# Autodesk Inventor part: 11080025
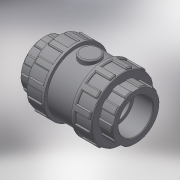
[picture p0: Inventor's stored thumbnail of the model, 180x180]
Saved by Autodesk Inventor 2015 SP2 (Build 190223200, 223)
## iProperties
Created: 2017-11
Part Number: 11080025
Material: Generic
Description: PLASSON CHECK VALVE CEM 25 PTFE COATED SPRING + EPDM O-RING
Document SubType Name: Modeling
Designer: KIM
Density: 1 g/cm^3
Appearance: Default
Author: KIM
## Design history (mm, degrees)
derived "110800 - 110600 110900-110000.ipt"
feature "Solid1::110800 - 110600 110900-110000.ipt"
tag "TaggingFeature1"
body "Solid1"
other parameters: "d0" = 89, "d1" = 25, "d2" = 55, "d3" = 19, "d5" = 13.3, "d7" = 35, "d8" = 49.5, "d13" = 0.75, "d23" = 19, "d24" = 52.8, "d25" = 0.5, "d26" = 0.75, "d27" = 8.25, "d28" = 4.125, "d29" = 14.25, "d30" = 0, "d35" = 0.75, "d39" = 27.5, "d45" = 360 deg, "d47" = 0.5, "d50" = 27.5, "d51" = 16.5, "d53" = 0, "d54" = 1.1, "d55" = 5, "d56" = 2.5, "d57" = 13.3, "d58" = 0, "d59" = 0.75, "d61" = 360 deg, "d_" = 25, "l_" = 19, "H_" = 89, "K_" = 55
